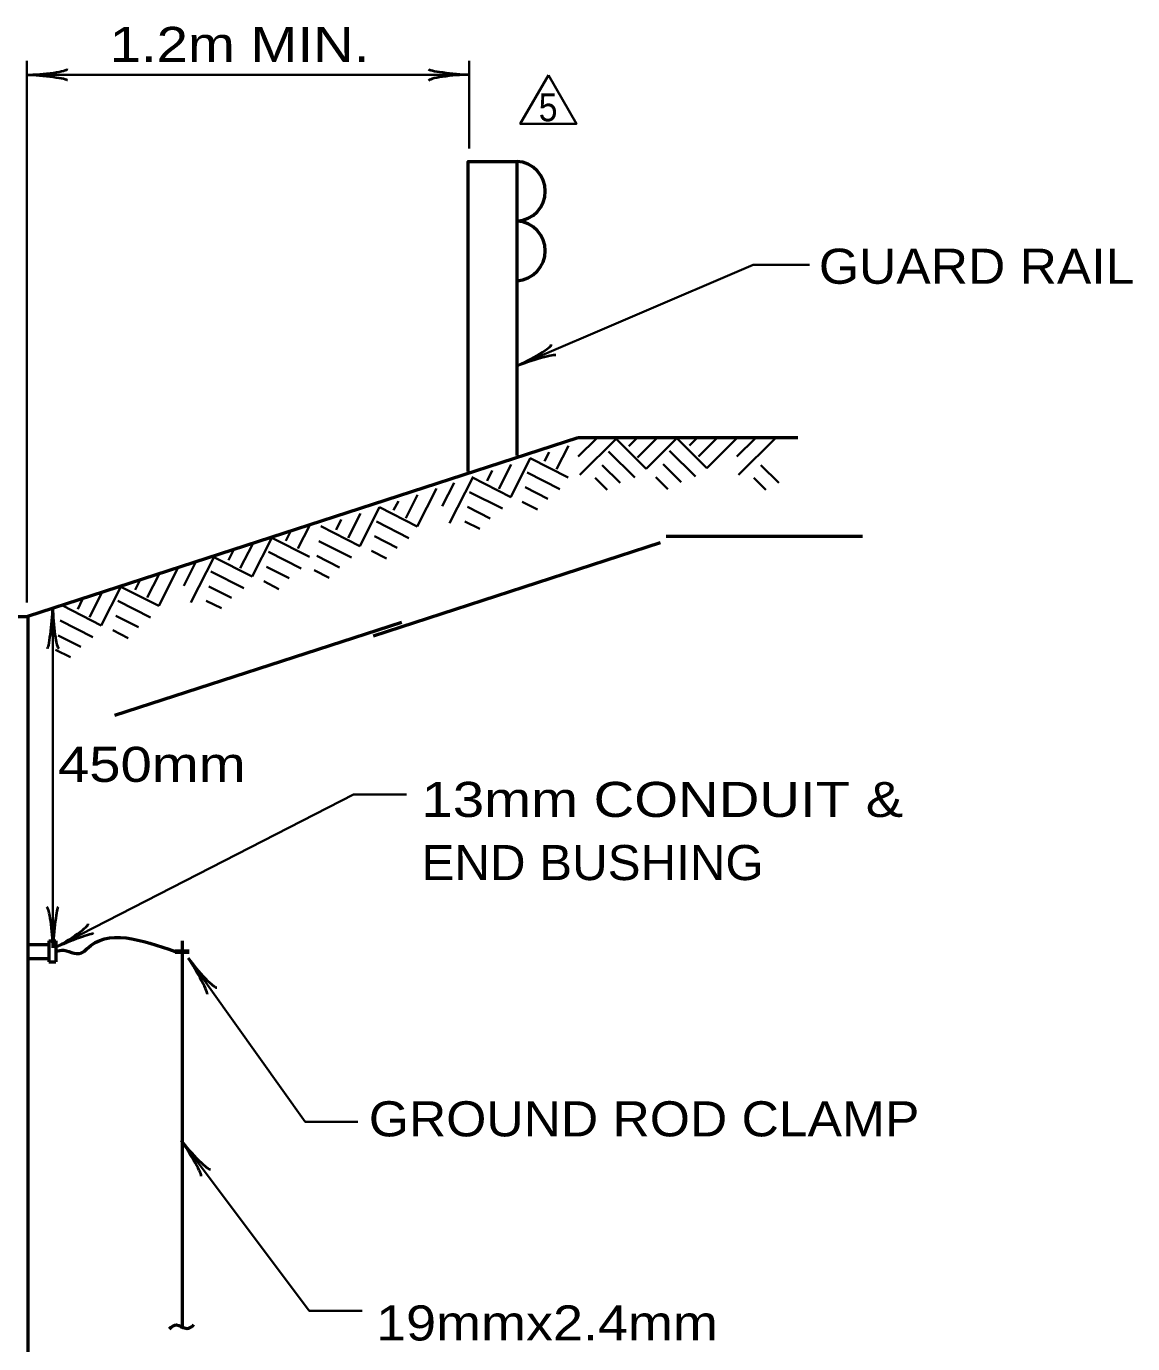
# Model space of a CAD drawing. Extents: x -34 to 822, y -23 to 521.
# Drawn here: x 113.8 to 208.4, y 193.9 to 306.6 of the extents above; entities that cross this region are included whole.
import ezdxf

# ---------------------------------------------------------------- set-up
doc = ezdxf.new("R2010")
doc.units = 0
doc.header["$LTSCALE"] = 1.2
doc.linetypes.add('LONG_DASHED', pattern=[7.5, 6, -1.5])
doc.layers.add('1', color=7, linetype='Continuous', lineweight=35)

msp = doc.modelspace()

# ---------------------------------------------------------------- linework, layer by layer
at = {"layer": '1'}
for p, q in [((113.887, 257.289), (113.887, 303.625)), ((151.69, 296.139), (151.69, 303.625)), ((113.887, 302.425), (151.69, 302.425)), ((175.988, 286.178), (155.74, 277.517)), ((175.988, 286.178), (180.788, 286.178)), ((160.18, 270.695), (159.163, 268.699)), ((162.609, 271.357), (161.025, 269.773)), ((164.313, 271.357), (161.169, 268.213)), ((164.193, 271.357), (166.833, 268.717)), ((166.017, 271.357), (165.345, 270.661)), ((167.745, 271.357), (166.089, 269.701)), ((169.449, 271.357), (166.833, 268.717)), ((169.449, 271.357), (172.017, 268.789)), ((171.153, 271.357), (170.529, 270.733)), ((172.881, 271.357), (171.297, 269.773)), ((174.585, 271.357), (172.017, 268.789)), ((176.169, 271.357), (174.585, 269.773)), ((177.873, 271.357), (174.729, 268.213)), ((156.916, 269.634), (155.244, 266.315)), ((156.916, 269.634), (160.152, 267.985)), ((158.537, 270.161), (158.136, 269.374)), ((163.617, 270.205), (165.849, 267.997)), ((168.825, 270.277), (171.033, 268.069)), ((153.652, 268.574), (153.228, 267.704)), ((155.296, 269.108), (154.233, 267.021)), ((156.657, 268.414), (159.439, 266.997)), ((163.065, 269.053), (164.601, 267.517)), ((168.273, 269.125), (169.809, 267.589)), ((176.625, 269.053), (178.161, 267.517)), ((150.411, 267.52), (149.394, 265.524)), ((152.032, 268.047), (150.013, 264.085)), ((151.918, 268.01), (155.244, 266.315)), ((156.488, 267.148), (158.423, 266.162)), ((162.465, 267.949), (163.497, 266.941)), ((167.649, 268.021), (168.681, 266.989)), ((176.025, 267.949), (177.057, 266.941)), ((145.641, 265.97), (145.24, 265.184)), ((147.284, 266.504), (146.267, 264.508)), ((148.905, 267.031), (147.256, 263.795)), ((151.726, 266.736), (154.531, 265.326)), ((142.4, 264.917), (141.336, 262.831)), ((144.02, 265.444), (142.348, 262.125)), ((144.02, 265.444), (147.256, 263.795)), ((151.557, 265.47), (153.492, 264.484)), ((156.235, 265.905), (157.536, 265.243)), ((138.074, 263.897), (137.057, 261.901)), ((139.021, 263.82), (142.348, 262.125)), ((140.756, 264.383), (140.332, 263.514)), ((143.76, 264.224), (146.543, 262.806)), ((151.327, 264.235), (152.62, 263.595)), ((134.81, 262.837), (133.138, 259.517)), ((134.81, 262.837), (138.046, 261.188)), ((136.43, 263.363), (136.03, 262.577)), ((143.591, 262.958), (145.527, 261.971)), ((131.546, 261.776), (131.122, 260.906)), ((133.189, 262.31), (132.126, 260.223)), ((134.55, 261.617), (137.332, 260.199)), ((138.83, 262.546), (141.635, 261.136)), ((143.339, 261.715), (144.639, 261.052)), ((128.305, 260.723), (127.288, 258.727)), ((129.925, 261.249), (127.907, 257.288)), ((129.811, 261.212), (133.138, 259.517)), ((134.381, 260.35), (136.317, 259.364)), ((138.661, 261.28), (140.596, 260.294)), ((123.534, 259.173), (123.134, 258.387)), ((125.178, 259.707), (124.161, 257.711)), ((126.798, 260.233), (125.149, 256.998)), ((129.619, 259.939), (132.424, 258.529)), ((138.431, 260.044), (139.724, 259.405)), ((120.293, 258.12), (119.23, 256.033)), ((121.913, 258.646), (120.241, 255.327)), ((121.913, 258.646), (125.149, 256.998)), ((129.45, 258.673), (131.386, 257.686)), ((134.129, 259.108), (135.429, 258.445)), ((116.915, 257.022), (120.241, 255.327)), ((118.65, 257.586), (118.226, 256.716)), ((121.654, 257.426), (124.436, 256.009)), ((129.221, 257.437), (130.514, 256.797)), ((116.099, 256.807), (116.099, 227.769)), ((121.485, 256.16), (123.42, 255.174)), ((116.723, 255.748), (119.528, 254.338)), ((121.233, 254.917), (122.533, 254.255)), ((116.554, 254.482), (118.489, 253.496)), ((116.325, 253.247), (117.618, 252.607)), ((141.817, 240.871), (116.287, 227.769)), ((141.817, 240.871), (146.335, 240.871)), ((127.687, 226.869), (137.669, 212.871)), ((137.669, 212.871), (142.188, 212.871)), ((138.016, 196.707), (127.087, 211.269)), ((138.016, 196.707), (142.534, 196.707))]:
    msp.add_line(p, q, dxfattribs=at)
at = {"layer": '1', "lineweight": 53}
for p, q in [((155.804, 269.863), (155.804, 295.021)), ((113.951, 256.11), (161.025, 271.405)), ((161.025, 271.405), (179.804, 271.405)), ((168.537, 262.966), (185.337, 262.966)), ((143.505, 254.447), (168.042, 262.42)), ((83.951, 256.089), (113.951, 256.089)), ((113.951, 256.11), (113.951, 135.467)), ((121.399, 247.649), (145.936, 255.622)), ((113.951, 228.047), (115.751, 228.047)), ((115.751, 228.347), (115.751, 226.547)), ((115.751, 228.347), (116.351, 228.347)), ((116.351, 228.347), (116.351, 226.547)), ((127.151, 228.347), (127.151, 195.347)), ((113.951, 226.847), (115.751, 226.847)), ((115.751, 226.547), (116.351, 226.547))]:
    msp.add_line(p, q, dxfattribs=at)
at = {"layer": '1', "linetype": 'LONG_DASHED', "lineweight": 53}
for p, q in [((105.209, 228.047), (113.951, 228.047)), ((105.209, 226.847), (113.951, 226.847))]:
    msp.add_line(p, q, dxfattribs=at)
at = {"layer": '1', "lineweight": 70}
msp.add_line((126.551, 227.447), (127.751, 227.447), dxfattribs=at)
at = {"layer": '1'}
msp.add_lwpolyline([(158.466, 302.388), (156.066, 298.231), (160.866, 298.231)], close=True, dxfattribs=at)
at = {"layer": '1', "lineweight": 53}
msp.add_lwpolyline([(151.604, 268.498), (151.604, 295.021), (155.804, 295.021)], dxfattribs=at)
for centre in [(155.649, 292.471), (155.649, 287.371)]:
    msp.add_arc(centre, 2.555, 273.47141, 86.52859, dxfattribs=at)
at = {"layer": '1', "lineweight": 40}
for centre, major_axis, ratio, start_param, end_param in [((115.196, 302.757), (-2.143, -0.187), 0.122415, 0.8963533, 3.1415927), ((115.196, 302.757), (-2.143, -0.187), 0.122415, 0.8963533, 3.1415927), ((115.232, 302.171), (-2.108, 0.211), 0.07063, 3.1407148, 5.41811), ((115.232, 302.171), (-2.108, 0.211), 0.07063, 3.1407148, 5.41811), ((150.37, 302.104), (2.143, 0.187), 0.122415, 0.8963533, 3.1415927), ((150.335, 302.689), (2.108, -0.211), 0.07063, 3.1407148, 5.41811), ((156.813, 278.337), (-1.896, -1.015), 0.122415, 0.8963533, 3.1415927), ((157.076, 277.812), (-2.021, -0.635), 0.07063, 3.1407148, 5.41811), ((115.845, 255.463), (0.211, 2.108), 0.07063, 3.1407148, 5.41811), ((115.845, 255.463), (0.211, 2.108), 0.07063, 3.1407148, 5.41811), ((116.43, 255.498), (-0.187, 2.143), 0.122415, 0.8963533, 3.1415927), ((116.43, 255.498), (-0.187, 2.143), 0.122415, 0.8963533, 3.1415927), ((115.767, 229.078), (0.187, -2.143), 0.122415, 0.8963533, 3.1415927), ((116.352, 229.113), (-0.211, -2.108), 0.07063, 3.1407148, 5.41811), ((117.301, 228.662), (-1.821, -1.145), 0.122415, 0.8963533, 3.1415927), ((117.599, 228.157), (-1.971, -0.775), 0.07063, 3.1407148, 5.41811), ((128.261, 225.627), (1.052, -1.838), 0.07063, 6.2823074, 8.5597026), ((128.717, 225.995), (-1.397, 1.636), 0.122415, 0.8963533, 3.1415927), ((127.691, 210.041), (1.097, -1.812), 0.07063, 6.2823074, 8.5597026), ((128.138, 210.42), (-1.436, 1.601), 0.122415, 0.8963533, 3.1415927)]:
    msp.add_ellipse(centre, major_axis=major_axis, ratio=ratio, start_param=start_param, end_param=end_param, dxfattribs=at)
at = {"layer": '1', "lineweight": 53}
for points in [[(116.351, 227.447), (117.045, 227.553), (117.92, 227.289), (118.733, 227.411), (118.998, 227.655), (126.551, 227.447)], [(126.071, 195.176), (126.675, 195.493), (127.459, 195.206), (127.716, 195.221), (128.168, 195.523)]]:
    msp.add_spline(points, degree=3, dxfattribs=at)

# ---------------------------------------------------------------- texts
at = {"layer": '1'}
for s, height, width, p in [('1.2m MIN.', 3, 1.2, (120.962, 303.531)), ('5', 2.4, 0.9, (157.641, 298.456)), ('GUARD RAIL', 3, 1.1, (181.595, 284.557)), ('450mm', 3, 1.2, (116.532, 241.948)), ('13mm CONDUIT &', 3, 1.2, (147.622, 238.948)), ('END BUSHING', 3, 1.05, (147.622, 233.548)), ('GROUND ROD CLAMP', 3, 1.1, (143.114, 211.626)), ('19mmx2.4mm', 3, 1.15, (143.736, 194.165))]:
    msp.add_text(s, height=height, dxfattribs=dict(at, width=width)).set_placement(p)

doc.saveas('drawing.dxf')
